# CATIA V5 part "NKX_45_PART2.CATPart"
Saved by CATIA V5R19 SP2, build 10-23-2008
Part number: NKX_45_PART2
Bounding box of the stored display mesh (mm): x 15.1 to 30.9, y 22.561 to 25.439, z -1.439 to 1.439
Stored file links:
  G:\EU_thinkMotion\CFAO_2010\MMS_groupe2\MMS_groupe2\OK\nrosalie\nrosalie_cfao_support_d_arme_legere_final\NKX_45_PART2.CATPart
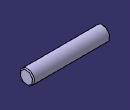
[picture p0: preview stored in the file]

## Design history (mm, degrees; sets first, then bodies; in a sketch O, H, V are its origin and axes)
Set1
  Point1: (0, 0, 0)
  Point2: (1, 0, 0)
  Point3: (0, 1, 0)
  Plane1: type 3Points, Element1 Point1, Element2 Point2, Element3 Point3
Body1 (main body)
  Sketch1 on Plane1, origin (0, 0, 0), H (1, 0, 0), V (0, 1, 0)
    point P1 (15.1, 24)
    point P2 (15.1, 25.3)
    line L1 (15.1, 24) -> (15.1, 25.3)
    arc A1 centre (15.3, 25.3) radius 0.2 from (15.3, 25.5) to (15.1, 25.3) ccw
    point P3 (15.3, 25.5)
    point P4 (30.7, 25.5)
    line L2 (15.3, 25.5) -> (30.7, 25.5)
    arc A2 centre (30.7, 25.3) radius 0.2 from (30.9, 25.3) to (30.7, 25.5) ccw
    point P5 (30.9, 25.3)
    point P6 (30.9, 24)
    line L3 (30.9, 25.3) -> (30.9, 24)
    point P7 (30.9, 24)
    point P8 (15.1, 24)
    line L4 (30.9, 24) -> (15.1, 24)
    point P9 (30.9, 24)
    point P10 (15.1, 24)
    axis line L5 (30.9, 24) -> (15.1, 24)
    point P11 (15.1, 24)
    point P12 (15.1, 25.3)
    point P13 (15.3, 25.5)
    point P14 (15.1, 25.3)
    point P15 (15.3, 25.5)
    point P16 (30.7, 25.5)
    point P17 (30.9, 25.3)
    point P18 (30.7, 25.5)
    point P19 (30.9, 25.3)
    point P20 (30.9, 24)
    point P21 (30.9, 24)
    point P22 (15.1, 24)
    coincidence: P11 P22, P12 P14, P13 P15, P16 P18, P17 P19, P20 P21
  Shaft1: profile Sketch1, axis Sketch1.L5, angle 360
